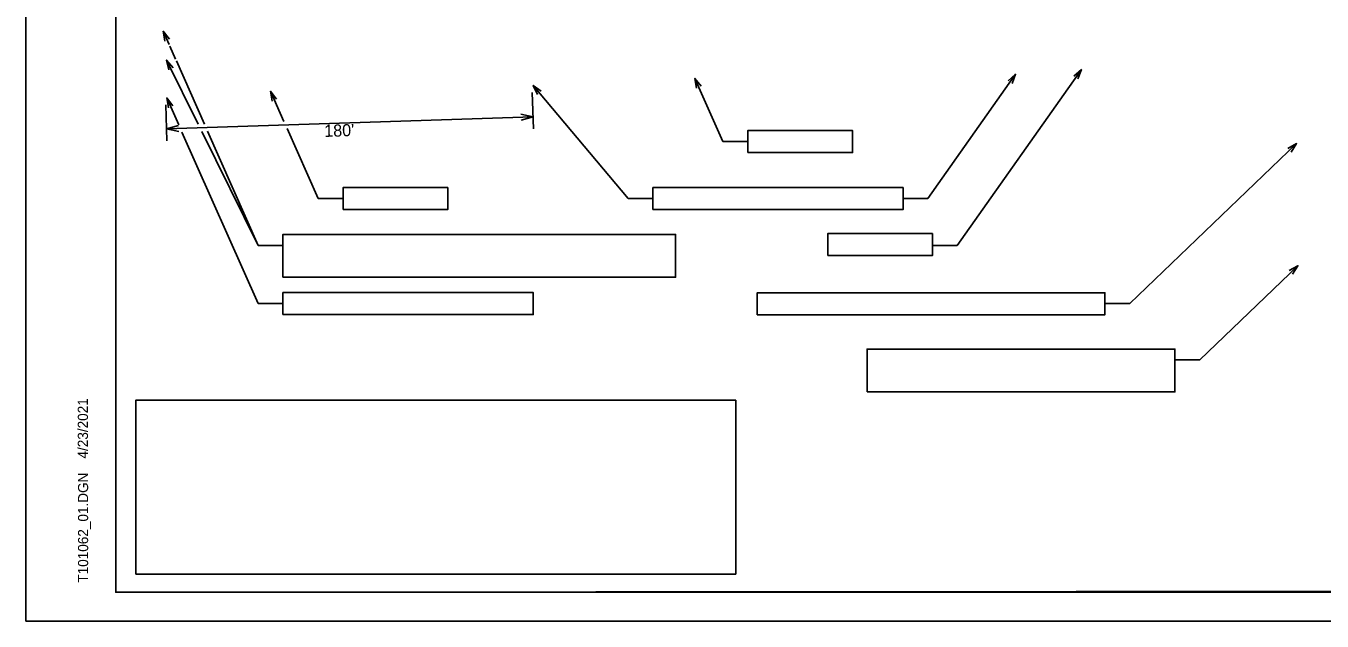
# Model space of a CAD drawing. Extents: x 1736833 to 1738623, y 544707 to 545544.
# Drawn here: x 1737623 to 1738161, y 544707 to 544953 of the extents above; entities that cross this region are included whole.
import ezdxf

# ---------------------------------------------------------------- set-up
doc = ezdxf.new("R2010")
doc.units = 0
for name, color, linetype in [('R_Border', 7, 'Continuous'), ('R_Dimension', 7, 'Continuous'), ('R_Draft', 7, 'Continuous'), ('R_No Plot', 7, 'Continuous'), ('T_Drafting', 7, 'Continuous'), ('T_Notes', 7, 'Continuous')]:
    doc.layers.add(name, color=color, linetype=linetype)

msp = doc.modelspace()

# ---------------------------------------------------------------- linework, layer by layer
at = {"layer": 'R_Border'}
for p, q in [((1737660.6, 544718.76), (1737660.6, 545335.14)), ((1737660.6, 544718.76), (1737660.6, 544718.76)), ((1738609.14, 544718.76), (1737660.6, 544718.76))]:
    msp.add_line(p, q, dxfattribs=at)
at = {"layer": 'R_Dimension'}
for p, q in [((1737833.24, 544925.79), (1737833.74, 544910.8)), ((1737681.32, 544920.73), (1737681.82, 544905.73)), ((1737681.66, 544910.73), (1737833.57, 544915.8))]:
    msp.add_line(p, q, dxfattribs=at)
for points in [[(1737828.53, 544916.88), (1737833.57, 544915.8), (1737828.62, 544914.38)], [(1737686.61, 544912.15), (1737681.66, 544910.73), (1737686.7, 544909.65)]]:
    msp.add_lwpolyline(points, dxfattribs=at)
at = {"layer": 'R_Draft'}
msp.add_lwpolyline([(1737660.6, 545335.14), (1738362.36, 545335.14), (1738362.36, 545305.5), (1738475, 545295.74), (1738536.2, 545296.37), (1738536.2, 545224.37), (1738536.2, 545185.59), (1738536.2, 545175.9), (1738608.92, 545175.9), (1738609.14, 544767.79), (1738408.07, 544767.79), (1738257.64, 544767.79), (1738257.64, 544719.22), (1737660.6, 544718.76)], close=True, dxfattribs=at)
at = {"layer": 'R_No Plot'}
msp.add_line((1737623.4, 544706.82), (1738623.4, 544706.82), dxfattribs=at)
msp.add_lwpolyline([(1737623.38, 545346.82), (1738623.4, 545346.82), (1738623.4, 544706.81), (1737623.38, 544706.81)], close=True, dxfattribs=at)
at = {"layer": 'T_Drafting'}
for p, q in [((1737680.31, 544951.21), (1737682.72, 544945.76)), ((1737683.07, 544944.97), (1737685.41, 544939.69)), ((1737681.71, 544939.25), (1737694.82, 544912.67)), ((1737685.73, 544938.96), (1737697.33, 544912.75)), ((1738033.6, 544933.37), (1737997.28, 544881.87)), ((1738060.86, 544935.33), (1738009.43, 544862.41)), ((1737833.64, 544928.76), (1737872.94, 544881.87)), ((1737900.66, 544931.64), (1737912.29, 544905.48)), ((1737681.73, 544923.56), (1737686.69, 544912.4)), ((1737724.76, 544926.36), (1737730.32, 544913.85)), ((1737688.01, 544909.44), (1737719.61, 544838.35)), ((1737696.28, 544909.72), (1737719.61, 544862.41)), ((1737698.64, 544909.8), (1737719.61, 544862.41)), ((1737731.63, 544910.9), (1737744.54, 544881.87)), ((1737912.29, 544905.48), (1737922.59, 544905.48)), ((1738150.04, 544904.64), (1738080.93, 544838.35)), ((1737744.54, 544881.87), (1737754.84, 544881.87)), ((1737872.94, 544881.87), (1737883.24, 544881.87)), ((1737986.98, 544881.87), (1737997.28, 544881.87)), ((1737719.61, 544862.41), (1737729.92, 544862.41)), ((1737999.13, 544862.41), (1738009.43, 544862.41)), ((1738150.63, 544854.07), (1738109.92, 544815.04)), ((1737719.61, 544838.35), (1737729.92, 544838.35)), ((1738070.63, 544838.35), (1738080.93, 544838.35)), ((1738099.62, 544815.04), (1738109.92, 544815.04))]:
    msp.add_line(p, q, dxfattribs=at)
for points in [[(1737681.01, 544947.15), (1737680.31, 544951.21), (1737682.84, 544947.96)], [(1737682.58, 544935.22), (1737681.71, 544939.25), (1737684.37, 544936.1)], [(1738030.48, 544930.67), (1738033.6, 544933.37), (1738032.11, 544929.52)], [(1738057.74, 544932.64), (1738060.86, 544935.33), (1738059.37, 544931.48)], [(1737835.44, 544925.05), (1737833.64, 544928.76), (1737836.98, 544926.34)], [(1737901.37, 544927.58), (1737900.66, 544931.64), (1737903.2, 544928.4)], [(1737682.44, 544919.5), (1737681.73, 544923.56), (1737684.27, 544920.31)], [(1737725.47, 544922.3), (1737724.76, 544926.36), (1737727.3, 544923.11)], [(1738146.47, 544902.59), (1738150.04, 544904.64), (1738147.85, 544901.15)], [(1738147.05, 544852.03), (1738150.63, 544854.07), (1738148.43, 544850.58)]]:
    msp.add_lwpolyline(points, dxfattribs=at)
for points in [[(1737922.59, 544900.92), (1737966, 544900.92), (1737966, 544910.04), (1737922.59, 544910.04)], [(1737754.84, 544877.31), (1737798.24, 544877.31), (1737798.24, 544886.43), (1737754.84, 544886.43)], [(1737883.24, 544877.31), (1737986.98, 544877.31), (1737986.98, 544886.43), (1737883.24, 544886.43)], [(1737729.92, 544849.25), (1737892.68, 544849.25), (1737892.68, 544867.05), (1737729.92, 544867.05)], [(1737955.73, 544858.26), (1737999.13, 544858.26), (1737999.13, 544867.38), (1737955.73, 544867.38)], [(1737729.92, 544833.79), (1737833.66, 544833.79), (1737833.66, 544842.91), (1737729.92, 544842.91)], [(1737926.53, 544833.74), (1738070.63, 544833.74), (1738070.63, 544842.86), (1737926.53, 544842.86)], [(1737972.01, 544801.74), (1738099.62, 544801.74), (1738099.62, 544819.54), (1737972.01, 544819.54)]]:
    msp.add_lwpolyline(points, close=True, dxfattribs=at)
at = {"layer": 'T_Notes'}
msp.add_lwpolyline([(1737668.9, 544726.27), (1737917.6, 544726.27), (1737917.6, 544798.32), (1737668.9, 544798.32)], close=True, dxfattribs=at)

# ---------------------------------------------------------------- texts
at = {"layer": 'R_Border'}
for s, p in [('4/23/2021', (1737649.08, 544774.15)), ('T101062_01.DGN', (1737649.17, 544722.73))]:
    msp.add_text(s, height=4.2, rotation=90, dxfattribs=at).set_placement(p)
at = {"layer": 'R_Dimension'}
msp.add_text("180'", height=5, rotation=1.9094, dxfattribs=at).set_placement((1737747.11, 544907.39))

doc.saveas('drawing.dxf')
